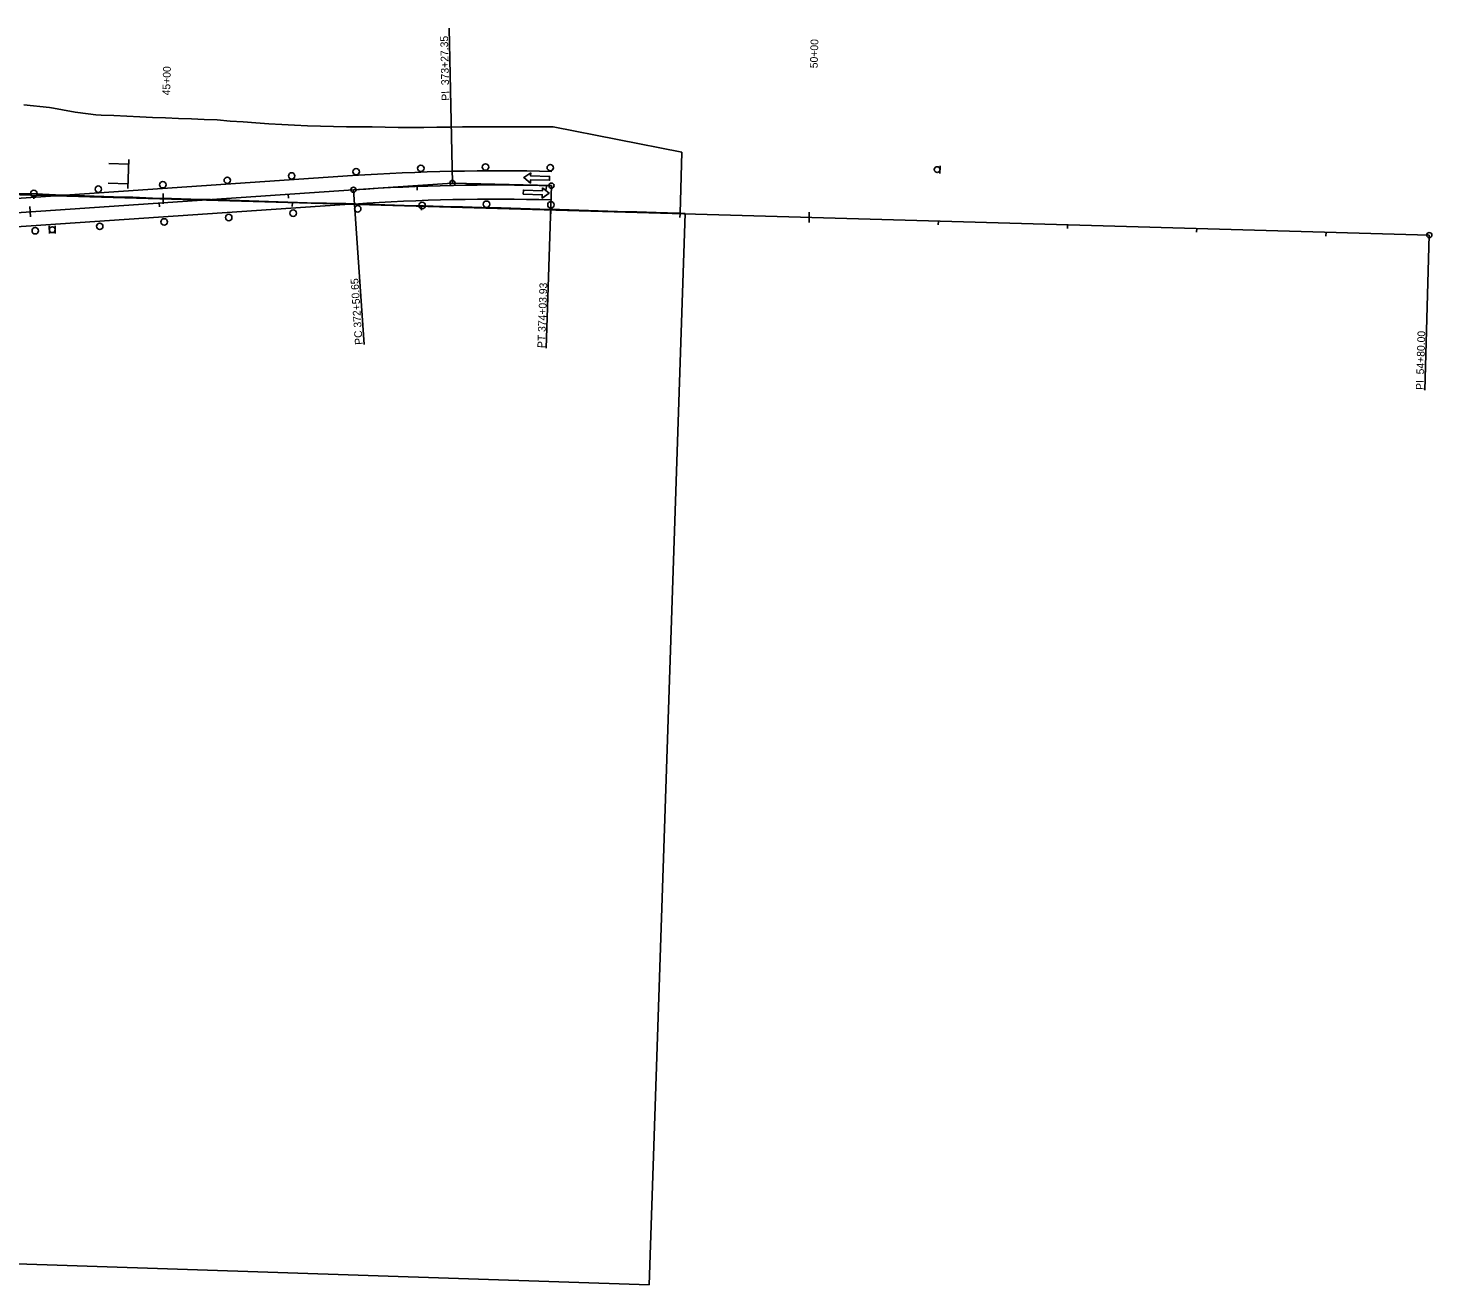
# Model space of a CAD drawing. Extents: x 976638 to 988477, y 1524676 to 1528093.
# Drawn here: x 983214 to 984300, y 1525464 to 1526437 of the extents above; entities that cross this region are included whole.
import ezdxf

# ---------------------------------------------------------------- set-up
doc = ezdxf.new("R2010")
doc.units = 0
for name, color, linetype in [('R_Draft', 7, 'Continuous'), ('R_Horz Alg', 7, 'Continuous'), ('R_Horz Alg Annot', 7, 'Continuous'), ('R_MOT', 7, 'Continuous'), ('R_No Plot', 7, 'Continuous'), ('R_Striping', 7, 'Continuous')]:
    doc.layers.add(name, color=color, linetype=linetype)

msp = doc.modelspace()

# ---------------------------------------------------------------- linework, layer by layer
at = {"layer": 'R_Draft'}
for p, q in [((983620.4, 1526360.5), (983720, 1526340.9)), ((983720, 1526340.9), (983718.6, 1526293.6))]:
    msp.add_line(p, q, dxfattribs=at)
for points in [[(983210.8, 1526377.5), (983230.7, 1526375.3), (983233.8, 1526374.9), (983240.7, 1526373.6), (983250.6, 1526371.7), (983260.6, 1526370.4), (983266.7, 1526369.7), (983270.6, 1526369.5), (983280.6, 1526369.1), (983290.5, 1526368.6), (983300.5, 1526368.2), (983310.5, 1526367.7), (983320.5, 1526367.3), (983330.5, 1526366.9), (983340.5, 1526366.5), (983350.5, 1526366.1), (983360.5, 1526365.7), (983370.5, 1526364.9), (983380.5, 1526364.2), (983390.4, 1526363.4), (983400.4, 1526362.7), (983410.4, 1526362.2), (983420.4, 1526361.7), (983430.4, 1526361.2), (983440.4, 1526360.8)], [(983440.4, 1526360.8), (983450.4, 1526360.7), (983460.4, 1526360.5), (983470.4, 1526360.4), (983480.4, 1526360.3), (983490.4, 1526360.2), (983500.4, 1526360), (983510.4, 1526359.9), (983520.4, 1526360), (983530.4, 1526360.2), (983540.4, 1526360.2), (983550.4, 1526360.3), (983560.4, 1526360.5), (983570.4, 1526360.5), (983580.4, 1526360.5), (983590.4, 1526360.5), (983600.4, 1526360.5), (983610.4, 1526360.5), (983620.4, 1526360.5)], [(983718.6, 1526293.6), (983670.1, 1526294.9), (983655.2, 1526295.4), (983640.2, 1526295.9), (983625.2, 1526296.3), (983610.2, 1526296.7), (983595.2, 1526297.2), (983580.2, 1526297.6), (983565.2, 1526298), (983550.2, 1526298.4), (983535.2, 1526298.8), (983520.1, 1526299.2), (983505.1, 1526299.6), (983490.1, 1526300.1), (983475.1, 1526300.6), (983460.1, 1526301.1), (983445.1, 1526301.4), (983430.2, 1526301.7), (983415.2, 1526302.2), (983400.2, 1526302.7), (983385.2, 1526303.2), (983370.2, 1526303.6), (983355.2, 1526304.2), (983340.2, 1526304.5), (983325.2, 1526304.9), (983310.3, 1526305.3), (983295.3, 1526305.9), (983280.3, 1526306.3), (983265.3, 1526306.8), (983250.3, 1526307.3), (983235.3, 1526307.9), (983220.3, 1526308.5), (983205.3, 1526308.9)]]:
    msp.add_lwpolyline(points, dxfattribs=at)
at = {"layer": 'R_Horz Alg'}
for p, q in [((981519.5, 1526356.3), (984298.3, 1526276.6)), ((983174.9, 1526291.9), (983465.9, 1526311.7))]:
    msp.add_line(p, q, dxfattribs=at)
msp.add_arc((983576.8, 1524678.4), 1637, 88.5182, 93.883, dxfattribs=at)
at = {"layer": 'R_Horz Alg Annot'}
for p, q in [((983465.9, 1526311.7), (983542.5, 1526316.9)), ((983542.5, 1526316.9), (983619.1, 1526314.9))]:
    msp.add_line(p, q, dxfattribs=at)
for points in [[(983542.5, 1526316.9), (983540, 1526436.8)], [(983318.8, 1526308.7), (983318.6, 1526300.7)], [(983415.6, 1526305.3), (983415.4, 1526308.3)], [(983465.9, 1526311.7), (983474.1, 1526192)], [(983515.3, 1526311.3), (983515.2, 1526314.3)], [(983619.1, 1526314.9), (983614.9, 1526189.1)], [(983615.1, 1526312), (983615.2, 1526315)], [(983215.6, 1526298.7), (983216.1, 1526290.7)], [(983218.7, 1526304.6), (983218.8, 1526307.6)], [(983315.8, 1526298.5), (983315.6, 1526301.5)], [(983418.6, 1526298.8), (983418.7, 1526301.8)], [(983518.6, 1526296), (983518.6, 1526299)], [(983618.5, 1526293.1), (983618.6, 1526296.1)], [(983718.5, 1526290.2), (983718.6, 1526293.2)], [(983818.6, 1526294.4), (983818.4, 1526286.4)], [(983918.4, 1526284.5), (983918.5, 1526287.5)], [(984018.3, 1526281.6), (984018.4, 1526284.6)], [(984118.3, 1526278.8), (984118.4, 1526281.8)], [(984218.3, 1526275.9), (984218.4, 1526278.9)], [(984298.3, 1526276.6), (984294.9, 1526156.7)]]:
    msp.add_lwpolyline(points, dxfattribs=at)
for centre in [(983465.9, 1526311.7), (983542.5, 1526316.9), (983619.1, 1526314.9), (984298.3, 1526276.6)]:
    msp.add_circle(centre, 2, dxfattribs=at)
at = {"layer": 'R_MOT'}
for p, q in [((983276.6, 1526332), (983291.9, 1526331.5)), ((983292, 1526335.2), (983291.3, 1526312.7)), ((983919.8, 1526330.2), (983919.6, 1526324.2)), ((983276, 1526316.8), (983291.4, 1526316.2)), ((983230.7, 1526277.8), (983230.5, 1526283.8)), ((983235, 1526283.9), (983235.2, 1526277.9))]:
    msp.add_line(p, q, dxfattribs=at)
for centre, radius in [((983518, 1526328.3), 2.5), ((983568.1, 1526329.3), 2.5), ((983618.2, 1526328.8), 2.5), ((983368.3, 1526319), 2.5), ((983418.1, 1526322.4), 2.5), ((983468, 1526325.7), 2.5), ((983917.5, 1526327.3), 2.25), ((983218.6, 1526308.8), 2.5), ((983268.5, 1526312.2), 2.5), ((983318.4, 1526315.6), 2.5), ((983469.2, 1526296.9), 2.5), ((983519, 1526299.5), 2.5), ((983568.8, 1526300.5), 2.5), ((983618.7, 1526300), 2.5), ((983319.5, 1526286.8), 2.5), ((983369.4, 1526290.2), 2.5), ((983419.3, 1526293.6), 2.5), ((983219.7, 1526280), 2.5), ((983232.9, 1526280.8), 2.25), ((983232.9, 1526280.8), 2.25), ((983269.6, 1526283.4), 2.5)]:
    msp.add_circle(centre, radius, dxfattribs=at)
at = {"layer": 'R_No Plot'}
for p, q in [((983694.8, 1525464.1), (983722.5, 1526293.3)), ((983694.8, 1525464.1), (983722.5, 1526293.3)), ((982073.4, 1525518.1), (983694.8, 1525464.1)), ((982073.4, 1525518.1), (983694.8, 1525464.1))]:
    msp.add_line(p, q, dxfattribs=at)
msp.add_lwpolyline([(983722.5, 1526293.3), (983700.1, 1526294), (983685.1, 1526294.5), (983670.1, 1526294.9), (983655.2, 1526295.4), (983640.2, 1526295.9), (983625.2, 1526296.3), (983610.2, 1526296.7), (983595.2, 1526297.2), (983580.2, 1526297.6), (983565.2, 1526298), (983550.2, 1526298.4), (983535.2, 1526298.8), (983520.1, 1526299.2), (983505.1, 1526299.6), (983490.1, 1526300.1), (983475.1, 1526300.6), (983460.1, 1526301.1), (983445.1, 1526301.4), (983430.2, 1526301.7), (983415.2, 1526302.2), (983400.2, 1526302.7), (983385.2, 1526303.2), (983370.2, 1526303.6), (983355.2, 1526304.2), (983340.2, 1526304.5), (983325.2, 1526304.9), (983310.3, 1526305.3), (983295.3, 1526305.9), (983280.3, 1526306.3), (983265.3, 1526306.8), (983250.3, 1526307.3), (983235.3, 1526307.9), (983220.3, 1526308.5), (983205.3, 1526308.9)], dxfattribs=at)
msp.add_lwpolyline([(983722.5, 1526293.3), (983700.1, 1526294), (983685.1, 1526294.5), (983670.1, 1526294.9), (983655.2, 1526295.4), (983640.2, 1526295.9), (983625.2, 1526296.3), (983610.2, 1526296.7), (983595.2, 1526297.2), (983580.2, 1526297.6), (983565.2, 1526298), (983550.2, 1526298.4), (983535.2, 1526298.8), (983520.1, 1526299.2), (983505.1, 1526299.6), (983490.1, 1526300.1), (983475.1, 1526300.6), (983460.1, 1526301.1), (983445.1, 1526301.4), (983430.2, 1526301.7), (983415.2, 1526302.2), (983400.2, 1526302.7), (983385.2, 1526303.2), (983370.2, 1526303.6), (983355.2, 1526304.2), (983340.2, 1526304.5), (983325.2, 1526304.9), (983310.3, 1526305.3), (983295.3, 1526305.9), (983280.3, 1526306.3), (983265.3, 1526306.8), (983250.3, 1526307.3), (983235.3, 1526307.9), (983220.3, 1526308.5), (983205.3, 1526308.9)], dxfattribs=at)
at = {"layer": 'R_Striping'}
for p, q in [((983174.2, 1526302.9), (983465.2, 1526322.7)), ((983174.9, 1526291.9), (983465.9, 1526311.7)), ((983175.7, 1526281), (983466.7, 1526300.7))]:
    msp.add_line(p, q, dxfattribs=at)
for points in [[(983603.1, 1526324.9), (983597.7, 1526321.1), (983602.8, 1526316.9), (983602.9, 1526319.4), (983617.6, 1526319), (983617.7, 1526322), (983603, 1526322.4)], [(983612.2, 1526313.3), (983617.2, 1526309.1), (983611.9, 1526305.3), (983612, 1526307.8), (983597.3, 1526308.4), (983597.4, 1526311.4), (983612.1, 1526310.8)]]:
    msp.add_lwpolyline(points, close=True, dxfattribs=at)
for radius in [1648, 1637, 1626]:
    msp.add_arc((983576.8, 1524678.4), radius, 88.5182, 93.883, dxfattribs=at)

# ---------------------------------------------------------------- texts
at = {"layer": 'R_Horz Alg Annot'}
for s, rotation, p in [('PI  373+27.35', 91.2006, (983540.1, 1526380.7)), ('50+00', 88.3578, (983825, 1526405.7)), ('45+00', 88.3578, (983324, 1526384.7)), ('PC 372+50.65', 93.883, (983473.1, 1526191.9)), ('PT 374+03.93', 88.0901, (983614.2, 1526189.1)), ('PI  54+80.00', 88.3578, (984293.9, 1526156.7))]:
    msp.add_text(s, height=6, rotation=rotation, dxfattribs=at).set_placement(p)

doc.saveas('drawing.dxf')
